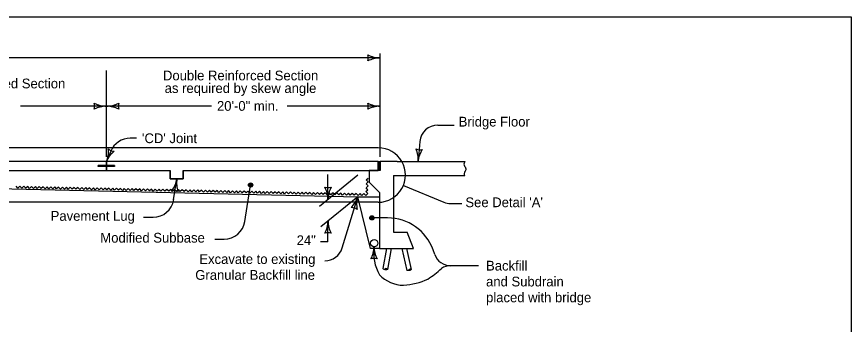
# Model space of a CAD drawing. Extents: x 9234 to 81668, y 5635 to 15999.
# Drawn here: x 15499 to 16868, y 9440 to 9944 of the extents above; entities that cross this region are included whole.
import ezdxf

# ---------------------------------------------------------------- set-up
doc = ezdxf.new("R2010")
doc.units = 0
for name, color, linetype in [('Level 61', 7, 'Continuous'), ('PS_BOLT', 7, 'Continuous'), ('PS_CONST', 7, 'Continuous'), ('PS_DAWA', 7, 'Continuous'), ('PS_DIM', 7, 'Continuous'), ('PS_SHAPE', 7, 'Continuous')]:
    doc.layers.add(name, color=color, linetype=linetype)

msp = doc.modelspace()

# ---------------------------------------------------------------- linework, layer by layer
at = {"layer": 'Level 61'}
msp.add_lwpolyline([(13732.5, 9944), (16867.5, 9944), (16867.5, 7924), (13732.5, 7924)], close=True, dxfattribs=at)
at = {"layer": 'PS_BOLT'}
for p, q in [((15646.6, 9706.7), (15290.2, 9706.7)), ((15633.2, 9698.3), (15633.2, 9700.2)), ((15633.2, 9700.2), (15659.9, 9700.2)), ((15633.2, 9698.3), (15633.2, 9700.2)), ((15633.2, 9700.2), (15646.6, 9700.2)), ((16092.1, 9706.7), (15646.6, 9706.7)), ((15646.6, 9706.7), (15646.6, 9700.2)), ((15646.6, 9700.2), (15646.6, 9706.7)), ((15646.6, 9700.2), (15659.9, 9700.2)), ((15659.9, 9700.2), (15646.6, 9700.2)), ((15659.9, 9700.2), (15659.9, 9698.3)), ((15659.9, 9700.2), (15659.9, 9698.3)), ((16092.1, 9691.8), (16092.1, 9706.7)), ((15290.2, 9691.8), (15646.6, 9691.8)), ((15646.6, 9698.3), (15633.2, 9698.3)), ((15659.9, 9698.3), (15646.6, 9698.3)), ((15646.6, 9698.3), (15646.6, 9691.8)), ((15646.6, 9691.8), (15646.6, 9698.3)), ((16054.9, 9691.8), (16077.2, 9691.8)), ((16077.2, 9691.8), (16092.1, 9691.8)), ((16092.1, 9691.8), (16092.1, 9691.8))]:
    msp.add_line(p, q, dxfattribs=at)
msp.add_lwpolyline([(15646.6, 9691.8), (15751.2, 9691.8), (15751.2, 9678.1), (15772.5, 9678.1), (15772.5, 9691.8), (16054.9, 9691.8)], dxfattribs=at)
at = {"layer": 'PS_CONST'}
for p, q in [((16189.8, 9766.3), (16216.5, 9766.3)), ((15695.8, 9744.7), (15685.5, 9744.7)), ((16092.1, 9729), (15288.9, 9729)), ((16160.2, 9739.2), (16157.4, 9706.7)), ((16160.2, 9739.2), (16157.4, 9706.7)), ((15653.5, 9723.4), (15646.6, 9706.7)), ((15756.7, 9644), (15762.1, 9678.1)), ((15873.3, 9608.2), (15882.8, 9668)), ((16133.2, 9667.4), (16199.4, 9640.1)), ((16032.8, 9564.8), (16058.4, 9648.8)), ((16092.1, 9639.9), (15288.9, 9639.9)), ((16210.8, 9637.8), (16229.1, 9637.8)), ((15707.3, 9615.1), (15722.9, 9615.1)), ((16107.4, 9614.2), (16081.6, 9614.2)), ((15824, 9579.3), (15839.5, 9579.3)), ((16184.7, 9554.1), (16181.9, 9561.7)), ((16256.5, 9535.7), (16210.8, 9535.7))]:
    msp.add_line(p, q, dxfattribs=at)
for points in [[(15882.5, 9671.1), (15883.7, 9670.6), (15885.5, 9670), (15885.9, 9668.2), (15885.6, 9666.6), (15884.4, 9665.1), (15882.7, 9665.2), (15880.9, 9665.5), (15880, 9666.9), (15879.9, 9668.5), (15880.9, 9670.5), (15882.3, 9670.6), (15884.1, 9670.2), (15885.6, 9669), (15885.5, 9667.3), (15884.4, 9665.9), (15882.7, 9665.7), (15880.9, 9666.1), (15880.6, 9667.1), (15880.3, 9668.4), (15881.1, 9669.9), (15882.4, 9669.8), (15884, 9669.6), (15885.1, 9668.7), (15884.5, 9667.2), (15883.4, 9666.3), (15881.8, 9666.3), (15881.5, 9667.1), (15881, 9668), (15881.7, 9669.2), (15882.8, 9669.5), (15883.9, 9669), (15883.9, 9667.9), (15883.4, 9667.1), (15882.4, 9666.8), (15881.9, 9667.2), (15881.6, 9667.8), (15882.1, 9668.7), (15882.8, 9668.9), (15883.5, 9668.5), (15883.4, 9667.9), (15882.9, 9667.5), (15882.2, 9667.5), (15882.2, 9668), (15882.8, 9668.3)], [(16081.9, 9611), (16080.7, 9611.5), (16078.9, 9612.1), (16078.5, 9613.9), (16078.8, 9615.5), (16080, 9617), (16081.7, 9616.9), (16083.5, 9616.6), (16084.4, 9615.2), (16084.5, 9613.6), (16083.5, 9611.6), (16082.1, 9611.5), (16080.3, 9611.9), (16078.8, 9613.1), (16078.9, 9614.8), (16080, 9616.2), (16081.7, 9616.4), (16083.5, 9616), (16083.8, 9615), (16084.1, 9613.8), (16083.3, 9612.2), (16082, 9612.3), (16080.4, 9612.5), (16079.3, 9613.4), (16079.9, 9614.9), (16081, 9615.8), (16082.6, 9615.8), (16083, 9615), (16083.4, 9614.1), (16082.7, 9612.9), (16081.6, 9612.6), (16080.6, 9613.1), (16080.5, 9614.3), (16081, 9615.1), (16082.1, 9615.3), (16082.5, 9614.9), (16082.8, 9614.3), (16082.3, 9613.4), (16081.6, 9613.2), (16080.9, 9613.6), (16081, 9614.2), (16081.5, 9614.6), (16082.2, 9614.6), (16082.2, 9614.1), (16081.6, 9613.8)]]:
    msp.add_lwpolyline(points, dxfattribs=at)
for centre in [(15882.8, 9668), (16081.6, 9614.2)]:
    msp.add_circle(centre, 3.47, dxfattribs=at)
for centre, radius, start, end in [((16189.8, 9736.6), 29.7, 90, 175.0304), ((15685.5, 9710), 34.7, 90, 157.4093), ((16092.1, 9684.4), 44.6, 270, 90.0004), ((15607.1, 9723.1), 42.7, 337.4082, 5.4807), ((15686, 9690.3), 42.7, 129.3357, 157.4082), ((15660.3, 9739.8), 16.5, 229.6748, 265.1415), ((16160.5, 9742.4), 16.5, 247.2977, 282.7644), ((16114.8, 9710.4), 42.7, 355.031, 23.1035), ((16160.5, 9742.4), 16.5, 247.2977, 282.7644), ((16114.8, 9710.4), 42.7, 355.031, 23.1035), ((16200, 9703), 42.7, 146.9585, 175.031), ((16200, 9703), 42.7, 146.9585, 175.031), ((15719.9, 9684.8), 42.7, 322.9382, 351.0107), ((15804.3, 9671.4), 42.7, 171.0107, 199.0832), ((15756.5, 9642.7), 16.5, 63.2773, 98.744), ((16017.5, 9661.2), 42.7, 314.9762, 343.0487), ((16099.3, 9636.3), 42.7, 163.0487, 191.1212), ((15722.9, 9649.4), 34.3, 270, 351.0107), ((16210.8, 9667.5), 29.7, 247.5504, 270), ((16048, 9614.5), 16.5, 55.3154, 90.7821), ((15839.5, 9613.6), 34.3, 270, 351.0107), ((16107.4, 9535), 79.2, 19.6988, 90), ((16004.4, 9573.5), 29.7, 270, 343.0465), ((16042.6, 9566.8), 42.5, 332.0355, 0.108), ((16156, 9556.1), 71.3, 171.4085, 209.4908), ((16127.6, 9567), 42.5, 180.108, 208.1804), ((16210.7, 9563.4), 27.7, 199.6981, 270), ((16085.2, 9531.3), 16.4, 72.3746, 107.8413), ((16084.3, 9651.1), 163.6, 303.0058, 312.8558), ((16210.7, 9508), 27.7, 90, 123.1752), ((16134, 9558.7), 55, 223.2802, 269.6675), ((16124.5, 9621.8), 118.5, 274.454, 294.4085)]:
    msp.add_arc(centre, radius, start, end, dxfattribs=at)
at = {"layer": 'PS_DAWA'}
for p, q in [((16095, 9714.1), (16095, 9883.9)), ((16092.1, 9876.5), (14221, 9876.5)), ((15646.6, 9714.1), (15646.6, 9855.8)), ((15646.6, 9797.3), (15505.4, 9797.3)), ((15818.6, 9797.3), (15646.6, 9797.3)), ((16092.1, 9797.3), (15942.7, 9797.3)), ((16058.4, 9684.1), (15995.6, 9632.9)), ((16009.6, 9644.3), (16009.6, 9685.5)), ((16058.4, 9648.8), (15998.2, 9599.7)), ((16009.6, 9575.1), (16009.6, 9609)), ((16009.6, 9575.1), (15997.2, 9575.1))]:
    msp.add_line(p, q, dxfattribs=at)
for centre, radius, start, end in [((16059.2, 9876.5), 16.5, 342.2667, 17.7334), ((16095, 9919.2), 42.7, 241.9275, 270), ((16095, 9833.7), 42.7, 90, 118.0725), ((15610.7, 9797.3), 16.5, 342.2667, 17.7334), ((15646.6, 9840), 42.7, 241.9275, 270), ((15646.6, 9754.5), 42.7, 90, 118.0725), ((15646.6, 9840), 42.7, 270, 298.0725), ((15646.6, 9754.5), 42.7, 61.9275, 90), ((15682.4, 9797.3), 16.5, 162.2666, 197.7334), ((16059.2, 9797.3), 16.5, 342.2667, 17.7334), ((16095, 9840), 42.7, 241.9275, 270), ((16095, 9754.5), 42.7, 90, 118.0725), ((16009.6, 9680.2), 16.5, 252.2666, 287.7334), ((15966.9, 9644.3), 42.7, 0, 28.0725), ((16052.4, 9644.3), 42.7, 151.9275, 180), ((15966.9, 9609), 42.7, 331.9275, 0), ((16052.4, 9609), 42.7, 180, 208.0725), ((16009.6, 9573.2), 16.5, 72.2666, 107.7334)]:
    msp.add_arc(centre, radius, start, end, dxfattribs=at)
at = {"layer": 'PS_DIM'}
for p, q in [((16092.1, 9706.7), (14937.2, 9706.7)), ((15659.9, 9700.2), (15633.2, 9700.2)), ((15633.2, 9700.2), (15633.2, 9698.3)), ((15659.9, 9700.2), (15633.2, 9700.2)), ((15633.2, 9700.2), (15633.2, 9698.3)), ((15646.6, 9706.7), (15646.6, 9700.2)), ((15659.9, 9700.2), (15659.9, 9698.3)), ((16092.1, 9706.7), (16092.1, 9691.7)), ((16092.1, 9706.7), (16095, 9706.7)), ((16092.1, 9706.3), (16095, 9706.3)), ((16123.3, 9706.7), (16095, 9706.7)), ((16095, 9706.7), (16095, 9691.7)), ((16123.3, 9706.7), (16233.9, 9706.7)), ((14950.8, 9691.8), (15751.2, 9691.8)), ((15659.9, 9698.3), (15633.2, 9698.3)), ((15659.9, 9698.3), (15633.2, 9698.3)), ((15646.6, 9691.8), (15646.6, 9698.3)), ((15772.5, 9691.8), (16092.1, 9691.8)), ((16054.9, 9691.8), (16078.2, 9691.8)), ((16077.2, 9691.8), (16077.2, 9672.5)), ((14941.2, 9674), (16058.4, 9648.8)), ((16117.3, 9683.8), (16117.3, 9590.9)), ((16117.3, 9683.8), (16233.9, 9683.8)), ((16077.2, 9672.5), (16094, 9655.7)), ((16079.1, 9564.1), (16058.4, 9648.8)), ((16058.4, 9648.8), (16094, 9648.8)), ((16094, 9655.7), (16094, 9564.1)), ((16117.3, 9590.9), (16139.7, 9590.9)), ((16150, 9564.1), (16139.7, 9590.9)), ((16094, 9564.1), (16079.1, 9564.1)), ((16094, 9564.1), (16150, 9564.1)), ((16105.7, 9564.1), (16099.7, 9531.1)), ((16113.3, 9564.1), (16107, 9529.8)), ((16130.9, 9564.1), (16138.8, 9527.8)), ((16138.5, 9564.1), (16146, 9529.3))]:
    msp.add_line(p, q, dxfattribs=at)
msp.add_lwpolyline([(15772.5, 9691.8), (15772.5, 9678.1), (15751.2, 9678.1), (15751.2, 9691.8)], dxfattribs=at)
msp.add_circle((16085.5, 9572.7), 5.94, dxfattribs=at)
for points in [[(16233.9, 9706.7), (16232.7, 9700.7), (16235.7, 9694.7), (16232.9, 9687.1), (16233.4, 9683.8)], [(16107, 9529.8), (16104.2, 9530.9), (16101.4, 9529.7), (16099.7, 9531.1)], [(16107, 9529.8), (16104.2, 9528.9), (16102.2, 9529.7)], [(16146, 9529.3), (16142.9, 9529.7), (16141.2, 9528), (16138.8, 9527.8)], [(16146, 9529.3), (16143.9, 9527.8), (16141.5, 9528)]]:
    msp.add_spline(points, degree=3, dxfattribs=at)
at = {"layer": 'PS_SHAPE'}
for p, q in [((16095, 9703.3), (16092.1, 9706.3)), ((16095, 9701.2), (16092.1, 9704.2)), ((16095, 9699.1), (16092.1, 9702.1)), ((16095, 9705.4), (16094.2, 9706.3)), ((16095, 9691.7), (16077.2, 9691.7)), ((16095, 9697), (16092.1, 9700)), ((16095, 9694.9), (16092.1, 9697.9)), ((16095, 9692.8), (16092.1, 9695.8)), ((16094, 9691.7), (16092.1, 9693.7))]:
    msp.add_line(p, q, dxfattribs=at)
for points in [[(16073.3, 9652.3), (16075, 9654), (16071.9, 9657.2), (16075.2, 9660.3), (16072.1, 9663.6), (16075.3, 9666.7), (16072.2, 9669.9), (16075.5, 9673), (16072.4, 9676.3), (16075.6, 9679.3), (16075.5, 9679.5)], [(15560.2, 9663.3), (15558.5, 9661.8), (15555.4, 9665), (15552.2, 9661.9), (15549.1, 9665.1), (15545.9, 9662), (15542.8, 9665.3), (15539.5, 9662.2), (15536.4, 9665.4), (15533.2, 9662.3), (15530.1, 9665.5), (15526.9, 9662.4), (15523.8, 9665.7), (15520.5, 9662.6), (15517.4, 9665.8), (15514.2, 9662.7), (15511.1, 9666), (15507.9, 9662.8), (15504.8, 9666.1), (15501.5, 9663), (15498.4, 9666.2)], [(15636.2, 9661.7), (15634.6, 9660.1), (15631.5, 9663.4), (15628.2, 9660.3), (15625.1, 9663.5), (15621.9, 9660.4), (15618.8, 9663.6), (15615.6, 9660.5), (15612.5, 9663.8), (15609.2, 9660.7), (15606.1, 9663.9), (15602.9, 9660.8), (15599.8, 9664.1), (15596.6, 9661), (15593.5, 9664.2), (15590.2, 9661.1), (15587.1, 9664.3), (15583.9, 9661.2), (15580.8, 9664.5), (15577.5, 9661.4), (15574.5, 9664.6), (15571.2, 9661.5), (15568.1, 9664.7), (15564.9, 9661.6), (15561.8, 9664.9), (15560.2, 9663.3)], [(15712.2, 9660.1), (15710.6, 9658.5), (15707.5, 9661.7), (15704.2, 9658.6), (15701.1, 9661.9), (15697.9, 9658.8), (15694.8, 9662), (15691.6, 9658.9), (15688.5, 9662.2), (15685.2, 9659.1), (15682.1, 9662.3), (15678.9, 9659.2), (15675.8, 9662.4), (15672.6, 9659.3), (15669.5, 9662.6), (15666.2, 9659.5), (15663.1, 9662.7), (15659.9, 9659.6), (15656.8, 9662.8), (15653.6, 9659.7), (15650.5, 9663), (15647.2, 9659.9), (15644.1, 9663.1), (15640.9, 9660), (15637.8, 9663.2), (15636.2, 9661.7)], [(15788.2, 9658.4), (15786.6, 9656.9), (15783.5, 9660.1), (15780.3, 9657), (15777.2, 9660.3), (15773.9, 9657.2), (15770.8, 9660.4), (15767.6, 9657.3), (15764.5, 9660.5), (15761.3, 9657.4), (15758.2, 9660.7), (15754.9, 9657.6), (15751.8, 9660.8), (15748.6, 9657.7), (15745.5, 9660.9), (15742.2, 9657.8), (15739.1, 9661.1), (15735.9, 9658), (15732.8, 9661.2), (15729.6, 9658.1), (15726.5, 9661.3), (15723.2, 9658.2), (15720.1, 9661.5), (15716.9, 9658.4), (15713.8, 9661.6), (15712.2, 9660.1)], [(15864.2, 9656.8), (15862.6, 9655.3), (15859.5, 9658.5), (15856.3, 9655.4), (15853.2, 9658.6), (15849.9, 9655.5), (15846.8, 9658.8), (15843.6, 9655.7), (15840.5, 9658.9), (15837.3, 9655.8), (15834.2, 9659), (15830.9, 9655.9), (15827.8, 9659.2), (15824.6, 9656.1), (15821.5, 9659.3), (15818.3, 9656.2), (15815.2, 9659.4), (15811.9, 9656.3), (15808.8, 9659.6), (15805.6, 9656.5), (15802.5, 9659.7), (15799.3, 9656.6), (15796.2, 9659.9), (15792.9, 9656.8), (15789.8, 9660), (15788.2, 9658.4)], [(15940.2, 9655.2), (15938.6, 9653.6), (15935.5, 9656.9), (15932.3, 9653.8), (15929.2, 9657), (15925.9, 9653.9), (15922.9, 9657.1), (15919.6, 9654), (15916.5, 9657.3), (15913.3, 9654.2), (15910.2, 9657.4), (15906.9, 9654.3), (15903.8, 9657.5), (15900.6, 9654.4), (15897.5, 9657.7), (15894.3, 9654.6), (15891.2, 9657.8), (15887.9, 9654.7), (15884.8, 9658), (15881.6, 9654.9), (15878.5, 9658.1), (15875.3, 9655), (15872.2, 9658.2), (15868.9, 9655.1), (15865.8, 9658.4), (15864.2, 9656.8)], [(16016.3, 9653.6), (16014.6, 9652), (16011.5, 9655.2), (16008.3, 9652.1), (16005.2, 9655.4), (16002, 9652.3), (15998.9, 9655.5), (15995.6, 9652.4), (15992.5, 9655.6), (15989.3, 9652.6), (15986.2, 9655.8), (15983, 9652.7), (15979.9, 9655.9), (15976.6, 9652.8), (15973.5, 9656.1), (15970.3, 9653), (15967.2, 9656.2), (15964, 9653.1), (15960.9, 9656.3), (15957.6, 9653.2), (15954.5, 9656.5), (15951.3, 9653.4), (15948.2, 9656.6), (15945, 9653.5), (15941.9, 9656.7), (15940.2, 9655.2)], [(16074.9, 9653.9), (16074.9, 9653.9), (16071.6, 9650.8), (16068.5, 9654), (16065.3, 9650.9), (16062.2, 9654.2), (16059, 9651.1), (16055.9, 9654.3), (16052.6, 9651.2), (16049.5, 9654.4), (16046.3, 9651.3), (16043.2, 9654.6), (16040, 9651.5), (16036.9, 9654.7), (16033.6, 9651.6), (16030.5, 9654.8), (16027.3, 9651.7), (16024.2, 9655), (16021, 9651.9), (16017.9, 9655.1), (16016.2, 9653.6)]]:
    msp.add_lwpolyline(points, dxfattribs=at)

# ---------------------------------------------------------------- texts
at = {"layer": 'PS_CONST'}
for s, p in [('Bridge Floor', (16224, 9763.9)), ("'CD' Joint", (15704.8, 9736.7)), ("See Detail 'A'", (16234.9, 9631.7)), ('Pavement Lug', (15555.1, 9609.4)), ('Modified Subbase', (15636.5, 9573.6)), ('Excavate to existing', (15798.8, 9538.6)), ('Backfill', (16268.8, 9527.8)), ('Granular Backfill line', (15792.1, 9512.6)), ('and Subdrain', (16268.8, 9501.8)), ('placed with bridge', (16268.8, 9475.8))]:
    msp.add_text(s, height=16, dxfattribs=at).set_placement(p)
at = {"layer": 'PS_DAWA'}
for s, p in [('Double Reinforced Section', (15739.2, 9839.6)), ('Single Reinforced Section', (15332.9, 9826.5)), ('as required by skew angle', (15742, 9818.9)), ('20\'-0" min.', (15827.7, 9789.7)), ('24"', (15958.3, 9569.5))]:
    msp.add_text(s, height=16, dxfattribs=at).set_placement(p)

doc.saveas('drawing.dxf')
